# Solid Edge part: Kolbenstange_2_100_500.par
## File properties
Username: ahadarics
Dokumentum tartalom típus: 0
Author: ahadarics
Last saved by: ahadarics
Revision: 88
Sűrűség: 0,000 kg/m^3
Pontosság: 0,990
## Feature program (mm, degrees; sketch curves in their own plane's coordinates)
base feature "unnamed BaseFeature 1"
thread "unnamed Thread 1"
chamfer "Letörés_1"  SetBackValue2 = 20 deg
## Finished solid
Body 1: solid body, 19 faces, 31 edges, 16 vertices.
  Faces by surface: plane 8, cylinder 5, cone 3, torus 3
  Edges by curve: circle 18, line 8, curve on surface 3, ellipse 2
Bounding box of the edges (mm; curved faces can reach further): 100.000 x 100.000 x 632.500, from (-50, -50, -78.75) to (50, 50, 553.75).
Cylindrical faces by radius (mm): R8.75 x1, R10 x1, R12.25 x1, R12.5 x1, R50 x1
Conical faces (half-angle, radius in mm at the cone's reference point): 20 deg R8.7989 x1, 30 deg R12.375 x1, 60 deg R9.375 x1
Toroidal faces (ring radius, tube radius in mm): R9.15 r0.4 x2, R10.45 r1.8 x1
Planar faces by outward normal: +x 1, +z 3, -x 1, -z 1, oblique 2
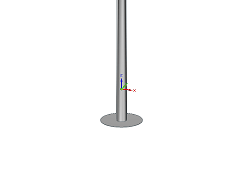
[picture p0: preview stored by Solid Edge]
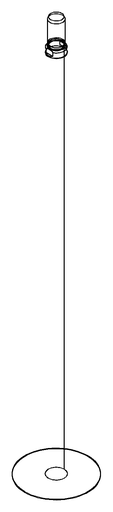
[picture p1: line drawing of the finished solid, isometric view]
